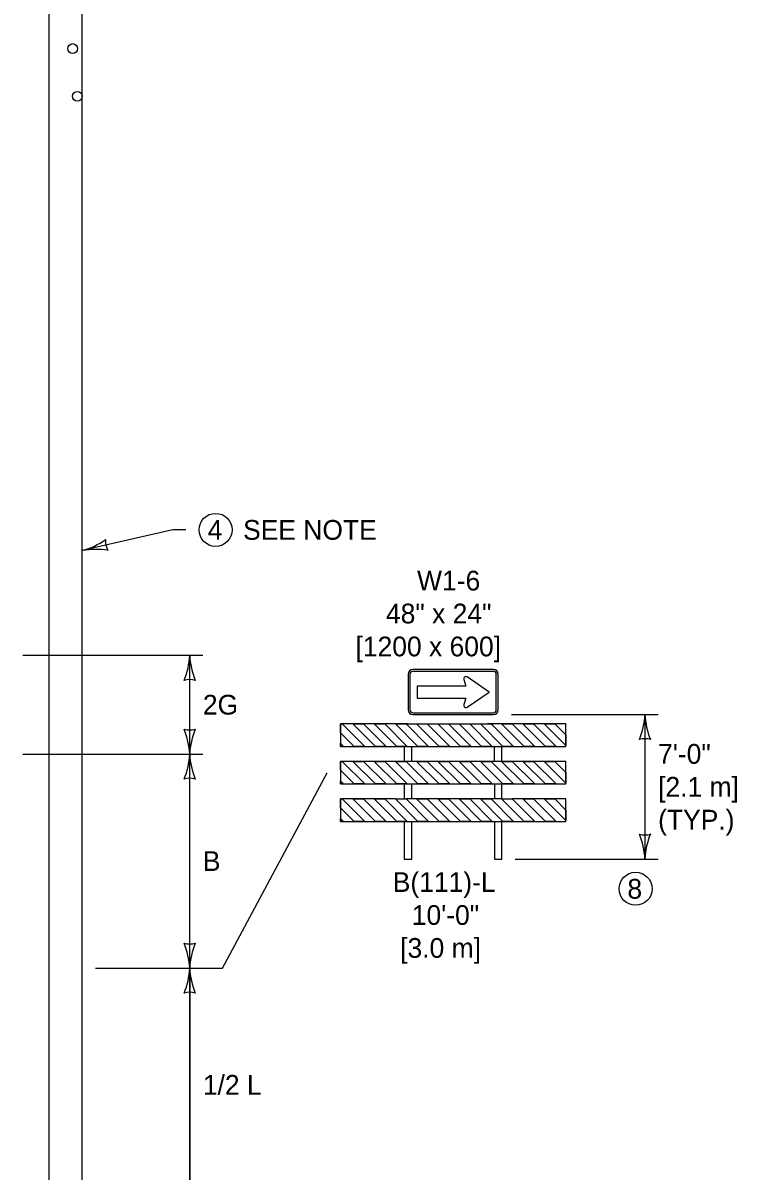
# Model space of a CAD drawing. Extents: x 49991.4 to 50021, y 49987.6 to 50011.4.
# Drawn here: x 50002.932 to 50005.099, y 50003.955 to 50007.442 of the extents above; entities that cross this region are included whole.
import ezdxf

# ---------------------------------------------------------------- set-up
doc = ezdxf.new("R2010")
doc.units = 0
for name, color, linetype in [('Level 1', 7, 'Continuous'), ('Level 2', 7, 'Continuous'), ('Level 3', 7, 'Continuous')]:
    doc.layers.add(name, color=color, linetype=linetype)

msp = doc.modelspace()

# ---------------------------------------------------------------- linework, layer by layer
at = {"layer": 'Level 1'}
for p, q in [((50003.0115, 50000.5714), (50003.0115, 50010.7538)), ((50003.1115, 50000.5714), (50003.1115, 50010.7538)), ((50004.3597, 50005.4783), (50004.1146, 50005.4783)), ((50004.3597, 50005.4726), (50004.1146, 50005.4726)), ((50004.1003, 50005.464), (50004.1003, 50005.3557)), ((50004.106, 50005.464), (50004.106, 50005.3557)), ((50004.2696, 50005.4477), (50004.276, 50005.4281)), ((50004.3466, 50005.4099), (50004.2801, 50005.4556)), ((50004.3682, 50005.3557), (50004.3682, 50005.464)), ((50004.3739, 50005.3557), (50004.3739, 50005.464)), ((50004.2658, 50005.4281), (50004.1276, 50005.4281)), ((50004.1276, 50005.4281), (50004.1276, 50005.3916)), ((50004.276, 50005.4281), (50004.2658, 50005.4281)), ((50004.2801, 50005.3642), (50004.3466, 50005.4099)), ((50004.1276, 50005.3916), (50004.276, 50005.3916)), ((50004.276, 50005.3916), (50004.2696, 50005.372)), ((50004.1146, 50005.3472), (50004.3597, 50005.3472)), ((50004.1146, 50005.3415), (50004.3597, 50005.3415)), ((50003.9691, 50005.2446), (50003.9007, 50005.313)), ((50003.9007, 50005.313), (50003.9691, 50005.2446)), ((50004.0014, 50005.2446), (50003.933, 50005.313)), ((50004.0014, 50005.2446), (50003.933, 50005.313)), ((50004.0336, 50005.2446), (50003.9652, 50005.313)), ((50003.9652, 50005.313), (50004.0336, 50005.2446)), ((50004.0658, 50005.2446), (50003.9975, 50005.313)), ((50004.0658, 50005.2446), (50003.9975, 50005.313)), ((50004.0981, 50005.2446), (50004.0297, 50005.313)), ((50004.0297, 50005.313), (50004.0981, 50005.2446)), ((50004.1304, 50005.2446), (50004.062, 50005.313)), ((50004.1626, 50005.2446), (50004.0942, 50005.313)), ((50004.0942, 50005.313), (50004.1341, 50005.313)), ((50004.1146, 50005.313), (50004.3597, 50005.313)), ((50004.1948, 50005.2446), (50004.1264, 50005.313)), ((50004.227, 50005.2446), (50004.1586, 50005.313)), ((50004.2592, 50005.2446), (50004.1908, 50005.313)), ((50004.2914, 50005.2446), (50004.223, 50005.313)), ((50004.3236, 50005.2446), (50004.2552, 50005.313)), ((50004.3558, 50005.2446), (50004.2874, 50005.313)), ((50004.3882, 50005.2446), (50004.3198, 50005.313)), ((50004.3739, 50005.313), (50004.3426, 50005.313)), ((50004.4205, 50005.2446), (50004.3521, 50005.313)), ((50004.4527, 50005.2446), (50004.3843, 50005.313)), ((50004.4527, 50005.2446), (50004.3843, 50005.313)), ((50004.4849, 50005.2446), (50004.4165, 50005.313)), ((50004.4165, 50005.313), (50004.4849, 50005.2446)), ((50004.5172, 50005.2446), (50004.4488, 50005.313)), ((50004.5172, 50005.2446), (50004.4488, 50005.313)), ((50004.5494, 50005.2446), (50004.481, 50005.313)), ((50004.481, 50005.313), (50004.5494, 50005.2446)), ((50004.5791, 50005.2472), (50004.5133, 50005.313)), ((50004.5791, 50005.2472), (50004.5133, 50005.313)), ((50004.5791, 50005.2794), (50004.5455, 50005.313)), ((50004.5455, 50005.313), (50004.5791, 50005.2794)), ((50003.9369, 50005.2446), (50003.8951, 50005.2864)), ((50003.9369, 50005.2446), (50003.8951, 50005.2864)), ((50003.9047, 50005.2446), (50003.8951, 50005.2541)), ((50003.8951, 50005.2541), (50003.9047, 50005.2446)), ((50004.1117, 50005.199), (50004.1117, 50005.2446)), ((50004.3625, 50005.199), (50004.3625, 50005.2446)), ((50003.9691, 50005.1307), (50003.9007, 50005.199)), ((50003.9007, 50005.199), (50003.9691, 50005.1307)), ((50004.0014, 50005.1307), (50003.933, 50005.199)), ((50004.0014, 50005.1307), (50003.933, 50005.199)), ((50004.0336, 50005.1307), (50003.9652, 50005.199)), ((50003.9652, 50005.199), (50004.0336, 50005.1307)), ((50004.0658, 50005.1307), (50003.9975, 50005.199)), ((50004.0658, 50005.1307), (50003.9975, 50005.199)), ((50004.0981, 50005.1307), (50004.0297, 50005.199)), ((50004.0297, 50005.199), (50004.0981, 50005.1307)), ((50004.1003, 50005.1607), (50004.062, 50005.199)), ((50004.1003, 50005.1929), (50004.0942, 50005.199)), ((50004.1626, 50005.1307), (50004.1003, 50005.1929)), ((50004.1948, 50005.1307), (50004.1264, 50005.199)), ((50004.227, 50005.1307), (50004.1586, 50005.199)), ((50004.2593, 50005.1307), (50004.1909, 50005.199)), ((50004.2915, 50005.1307), (50004.2232, 50005.199)), ((50004.3237, 50005.1307), (50004.2554, 50005.199)), ((50004.356, 50005.1307), (50004.2876, 50005.199)), ((50004.3882, 50005.1307), (50004.3198, 50005.199)), ((50004.4205, 50005.1307), (50004.3521, 50005.199)), ((50004.4527, 50005.1307), (50004.3843, 50005.199)), ((50004.4527, 50005.1307), (50004.3843, 50005.199)), ((50004.4849, 50005.1307), (50004.4165, 50005.199)), ((50004.4165, 50005.199), (50004.4849, 50005.1307)), ((50004.5172, 50005.1307), (50004.4488, 50005.199)), ((50004.5172, 50005.1307), (50004.4488, 50005.199)), ((50004.5494, 50005.1307), (50004.481, 50005.199)), ((50004.481, 50005.199), (50004.5494, 50005.1307)), ((50004.5791, 50005.1332), (50004.5133, 50005.199)), ((50004.5791, 50005.1332), (50004.5133, 50005.199)), ((50004.5791, 50005.1654), (50004.5455, 50005.199)), ((50004.5455, 50005.199), (50004.5791, 50005.1654)), ((50003.9369, 50005.1307), (50003.8951, 50005.1724)), ((50003.9369, 50005.1307), (50003.8951, 50005.1724)), ((50004.1304, 50005.1307), (50004.1003, 50005.1607)), ((50003.9047, 50005.1307), (50003.8951, 50005.1402)), ((50003.8951, 50005.1402), (50003.9047, 50005.1307)), ((50003.9691, 50005.0167), (50003.9007, 50005.0851)), ((50003.9007, 50005.0851), (50003.9691, 50005.0167)), ((50004.0014, 50005.0167), (50003.933, 50005.0851)), ((50004.0014, 50005.0167), (50003.933, 50005.0851)), ((50004.0336, 50005.0167), (50003.9652, 50005.0851)), ((50003.9652, 50005.0851), (50004.0336, 50005.0167)), ((50004.0658, 50005.0167), (50003.9975, 50005.0851)), ((50004.0658, 50005.0167), (50003.9975, 50005.0851)), ((50004.0981, 50005.0167), (50004.0297, 50005.0851)), ((50004.0297, 50005.0851), (50004.0981, 50005.0167)), ((50004.1304, 50005.0167), (50004.062, 50005.0851)), ((50004.1304, 50005.0167), (50004.062, 50005.0851)), ((50004.1626, 50005.0167), (50004.0942, 50005.0851)), ((50004.0942, 50005.0851), (50004.1626, 50005.0167)), ((50004.1948, 50005.0167), (50004.1264, 50005.0851)), ((50004.1948, 50005.0167), (50004.1264, 50005.0851)), ((50004.227, 50005.0167), (50004.1586, 50005.0851)), ((50004.1586, 50005.0851), (50004.227, 50005.0167)), ((50004.2593, 50005.0167), (50004.1909, 50005.0851)), ((50004.2593, 50005.0167), (50004.1909, 50005.0851)), ((50004.2915, 50005.0167), (50004.2232, 50005.0851)), ((50004.2232, 50005.0851), (50004.2915, 50005.0167)), ((50004.3237, 50005.0167), (50004.2554, 50005.0851)), ((50004.3237, 50005.0167), (50004.2554, 50005.0851)), ((50004.356, 50005.0167), (50004.2876, 50005.0851)), ((50004.2876, 50005.0851), (50004.356, 50005.0167)), ((50004.3882, 50005.0167), (50004.3198, 50005.0851)), ((50004.3882, 50005.0167), (50004.3198, 50005.0851)), ((50004.4205, 50005.0167), (50004.3521, 50005.0851)), ((50004.3521, 50005.0851), (50004.4205, 50005.0167)), ((50004.4527, 50005.0167), (50004.3843, 50005.0851)), ((50004.4527, 50005.0167), (50004.3843, 50005.0851)), ((50004.4849, 50005.0167), (50004.4165, 50005.0851)), ((50004.4165, 50005.0851), (50004.4849, 50005.0167)), ((50004.5172, 50005.0167), (50004.4488, 50005.0851)), ((50004.5172, 50005.0167), (50004.4488, 50005.0851)), ((50004.5494, 50005.0167), (50004.481, 50005.0851)), ((50004.481, 50005.0851), (50004.5494, 50005.0167)), ((50004.5791, 50005.0192), (50004.5133, 50005.0851)), ((50004.5791, 50005.0192), (50004.5133, 50005.0851)), ((50004.5791, 50005.0515), (50004.5455, 50005.0851)), ((50004.5455, 50005.0851), (50004.5791, 50005.0515)), ((50003.9369, 50005.0167), (50003.8951, 50005.0584)), ((50003.9369, 50005.0167), (50003.8951, 50005.0584)), ((50003.9047, 50005.0167), (50003.8951, 50005.0262)), ((50003.8951, 50005.0262), (50003.9047, 50005.0167)), ((50003.4375, 50004.5714), (50003.4375, 50003.8622))]:
    msp.add_line(p, q, dxfattribs=at)
for points in [[(50004.1003, 50005.313), (50003.8951, 50005.313), (50003.8951, 50005.2446), (50004.1003, 50005.2446)], [(50003.8951, 50005.2864), (50003.8951, 50005.313), (50003.9007, 50005.313)], [(50003.933, 50005.313), (50003.9652, 50005.313)], [(50003.9975, 50005.313), (50004.0297, 50005.313)], [(50004.1626, 50005.2446), (50004.1304, 50005.2446), (50004.062, 50005.313), (50004.0942, 50005.313), (50004.1626, 50005.2446)], [(50004.1003, 50005.2446), (50004.5791, 50005.2446), (50004.5791, 50005.313), (50004.3739, 50005.313)], [(50004.1264, 50005.313), (50004.1341, 50005.313), (50004.1586, 50005.313), (50004.227, 50005.2446), (50004.1948, 50005.2446), (50004.1264, 50005.313)], [(50004.1908, 50005.313), (50004.223, 50005.313), (50004.2914, 50005.2446), (50004.2592, 50005.2446), (50004.1908, 50005.313)], [(50004.2552, 50005.313), (50004.2874, 50005.313), (50004.3558, 50005.2446), (50004.3236, 50005.2446), (50004.2552, 50005.313)], [(50004.3198, 50005.313), (50004.3426, 50005.313), (50004.3521, 50005.313), (50004.4205, 50005.2446), (50004.3882, 50005.2446), (50004.3198, 50005.313)], [(50004.3843, 50005.313), (50004.4165, 50005.313)], [(50004.4488, 50005.313), (50004.481, 50005.313)], [(50004.5133, 50005.313), (50004.5455, 50005.313)], [(50004.5791, 50005.2794), (50004.5791, 50005.2472)], [(50003.9047, 50005.2446), (50003.8951, 50005.2446), (50003.8951, 50005.2541)], [(50003.9691, 50005.2446), (50003.9369, 50005.2446)], [(50004.0336, 50005.2446), (50004.0014, 50005.2446)], [(50004.0981, 50005.2446), (50004.0658, 50005.2446)], [(50004.0889, 50005.2446), (50004.0889, 50005.199)], [(50004.3853, 50005.199), (50004.3853, 50005.2446)], [(50004.4849, 50005.2446), (50004.4527, 50005.2446)], [(50004.5494, 50005.2446), (50004.5172, 50005.2446)], [(50004.1003, 50005.199), (50003.8951, 50005.199), (50003.8951, 50005.1307), (50004.5791, 50005.1307), (50004.5791, 50005.199), (50004.1003, 50005.199)], [(50003.8951, 50005.1724), (50003.8951, 50005.199), (50003.9007, 50005.199)], [(50003.933, 50005.199), (50003.9652, 50005.199)], [(50003.9975, 50005.199), (50004.0297, 50005.199)], [(50004.1626, 50005.1307), (50004.1304, 50005.1307), (50004.1003, 50005.1607), (50004.062, 50005.199), (50004.0889, 50005.199), (50004.0942, 50005.199), (50004.1003, 50005.1929), (50004.1626, 50005.1307)], [(50004.1264, 50005.199), (50004.1586, 50005.199), (50004.227, 50005.1307), (50004.1948, 50005.1307), (50004.1264, 50005.199)], [(50004.1909, 50005.199), (50004.2232, 50005.199), (50004.2915, 50005.1307), (50004.2593, 50005.1307), (50004.1909, 50005.199)], [(50004.2554, 50005.199), (50004.2876, 50005.199), (50004.356, 50005.1307), (50004.3237, 50005.1307), (50004.2554, 50005.199)], [(50004.3198, 50005.199), (50004.3521, 50005.199), (50004.4205, 50005.1307), (50004.3882, 50005.1307), (50004.3198, 50005.199)], [(50004.3843, 50005.199), (50004.4165, 50005.199)], [(50004.4488, 50005.199), (50004.481, 50005.199)], [(50004.5133, 50005.199), (50004.5455, 50005.199)], [(50004.5791, 50005.1654), (50004.5791, 50005.1332)], [(50003.9047, 50005.1307), (50003.8951, 50005.1307), (50003.8951, 50005.1402)], [(50003.9691, 50005.1307), (50003.9369, 50005.1307)], [(50004.0336, 50005.1307), (50004.0014, 50005.1307)], [(50004.0981, 50005.1307), (50004.0658, 50005.1307)], [(50004.0889, 50005.1307), (50004.0889, 50005.0851)], [(50004.1117, 50005.0851), (50004.1117, 50005.1307)], [(50004.3625, 50005.1307), (50004.3625, 50005.0851)], [(50004.3853, 50005.0851), (50004.3853, 50005.1307)], [(50004.4849, 50005.1307), (50004.4527, 50005.1307)], [(50004.5494, 50005.1307), (50004.5172, 50005.1307)], [(50003.8951, 50005.0584), (50003.8951, 50005.0851), (50003.9007, 50005.0851)], [(50004.062, 50005.0851), (50003.8951, 50005.0851), (50003.8951, 50005.0167), (50004.5791, 50005.0167), (50004.5791, 50005.0851), (50004.4165, 50005.0851)], [(50003.933, 50005.0851), (50003.9652, 50005.0851)], [(50003.9975, 50005.0851), (50004.0297, 50005.0851)], [(50004.062, 50005.0851), (50004.0942, 50005.0851)], [(50004.3843, 50005.0851), (50004.0942, 50005.0851)], [(50004.1264, 50005.0851), (50004.1586, 50005.0851)], [(50004.1909, 50005.0851), (50004.2232, 50005.0851)], [(50004.2554, 50005.0851), (50004.2876, 50005.0851)], [(50004.3198, 50005.0851), (50004.3521, 50005.0851)], [(50004.3843, 50005.0851), (50004.4165, 50005.0851)], [(50004.4488, 50005.0851), (50004.481, 50005.0851)], [(50004.5133, 50005.0851), (50004.5455, 50005.0851)], [(50004.5791, 50005.0515), (50004.5791, 50005.0192)], [(50003.9047, 50005.0167), (50003.8951, 50005.0167), (50003.8951, 50005.0262)], [(50003.9691, 50005.0167), (50003.9369, 50005.0167)], [(50004.0336, 50005.0167), (50004.0014, 50005.0167)], [(50004.0981, 50005.0167), (50004.0658, 50005.0167)], [(50004.0889, 50005.0166), (50004.0889, 50004.9026), (50004.1117, 50004.9026), (50004.1117, 50005.0166)], [(50004.1626, 50005.0167), (50004.1304, 50005.0167)], [(50004.227, 50005.0167), (50004.1948, 50005.0167)], [(50004.2915, 50005.0167), (50004.2593, 50005.0167)], [(50004.356, 50005.0167), (50004.3237, 50005.0167)], [(50004.3625, 50005.0166), (50004.3625, 50004.9026), (50004.3853, 50004.9026), (50004.3853, 50005.0166)], [(50004.4205, 50005.0167), (50004.3882, 50005.0167)], [(50004.4849, 50005.0167), (50004.4527, 50005.0167)], [(50004.5494, 50005.0167), (50004.5172, 50005.0167)]]:
    msp.add_lwpolyline(points, dxfattribs=at)
for centre in [(50003.0824, 50007.3643), (50003.0964, 50007.2194)]:
    msp.add_circle(centre, 0.015, dxfattribs=at)
for centre, radius, start, end in [((50004.1146, 50005.464), 0.0142, 90, 180), ((50004.1146, 50005.464), 0.00855, 90, 180), ((50004.3597, 50005.464), 0.0142, 0, 90), ((50004.3597, 50005.464), 0.00855, 0, 90), ((50004.2762, 50005.4498), 0.00695, 55.4806, 197.9582), ((50004.2762, 50005.3699), 0.00695, 162.0418, 304.5194), ((50004.1146, 50005.3557), 0.0142, 180, 270), ((50004.1146, 50005.3557), 0.00855, 180, 270), ((50004.3597, 50005.3557), 0.0142, 270, 360), ((50004.3597, 50005.3557), 0.00855, 270, 360)]:
    msp.add_arc(centre, radius, start, end, dxfattribs=at)
at = {"layer": 'Level 2'}
for centre in [(50003.5162, 50005.9025), (50004.7911, 50004.8123)]:
    msp.add_circle(centre, 0.0501, dxfattribs=at)
at = {"layer": 'Level 3'}
for p, q in [((50003.3861, 50005.9025), (50003.1115, 50005.8397)), ((50003.4261, 50005.9025), (50003.3861, 50005.9025)), ((50002.9315, 50005.5214), (50003.4775, 50005.5214)), ((50003.4375, 50005.2214), (50003.4375, 50005.5214)), ((50004.4139, 50005.3415), (50004.8593, 50005.3415)), ((50004.8193, 50005.3415), (50004.8193, 50004.9026)), ((50002.9315, 50005.2214), (50003.4775, 50005.2214)), ((50003.4375, 50004.5714), (50003.4375, 50005.2214)), ((50003.5375, 50004.5714), (50003.8551, 50005.1649)), ((50004.4253, 50004.9026), (50004.8593, 50004.9026)), ((50003.1515, 50004.5714), (50003.5375, 50004.5714)), ((50003.222, 50004.5714), (50003.5375, 50004.5714)), ((50003.4375, 50003.8622), (50003.4375, 50004.5714))]:
    msp.add_line(p, q, dxfattribs=at)
for centre, radius, start, end in [((50003.053, 50006.0542), 0.2223, 285.2569, 305.4404), ((50003.2365, 50005.8683), 0.0548, 175.0353, 210.7576), ((50003.1523, 50005.6103), 0.233, 80.8193, 100.0691), ((50003.2154, 50005.5305), 0.2223, 337.456, 357.6395), ((50003.6702, 50005.5329), 0.233, 182.8273, 202.0772), ((50003.4375, 50005.3932), 0.0548, 72.1388, 107.8612), ((50004.5971, 50005.3506), 0.2223, 337.456, 357.6395), ((50005.052, 50005.353), 0.233, 182.8273, 202.0772), ((50003.4375, 50005.3496), 0.0548, 252.1388, 287.8612), ((50003.2048, 50005.2099), 0.233, 2.8273, 22.0772), ((50003.6596, 50005.2122), 0.2223, 157.456, 177.6395), ((50004.8193, 50005.2133), 0.0548, 72.1388, 107.8612), ((50003.2154, 50005.2305), 0.2223, 337.456, 357.6395), ((50003.6702, 50005.2329), 0.233, 182.8273, 202.0772), ((50003.4375, 50005.0932), 0.0548, 72.1388, 107.8612), ((50004.8193, 50005.0308), 0.0548, 252.1388, 287.8612), ((50004.5865, 50004.8911), 0.233, 2.8273, 22.0772), ((50005.0414, 50004.8935), 0.2223, 157.456, 177.6395), ((50003.4375, 50004.6996), 0.0548, 252.1388, 287.8612), ((50003.2048, 50004.5599), 0.233, 2.8273, 22.0772), ((50003.6596, 50004.5622), 0.2223, 157.456, 177.6395), ((50003.2154, 50004.5805), 0.2223, 337.456, 357.6395), ((50003.6702, 50004.5829), 0.233, 182.8273, 202.0772), ((50003.4375, 50004.4432), 0.0548, 72.1388, 107.8612)]:
    msp.add_arc(centre, radius, start, end, dxfattribs=at)

# ---------------------------------------------------------------- texts
at = {"layer": 'Level 2'}
for s, p in [('4', (50003.4922, 50005.8725)), ('SEE NOTE', (50003.5995, 50005.8724))]:
    msp.add_text(s, height=0.06, rotation=360, dxfattribs=at).set_placement(p)
for s, p in [('W1-6', (50004.1277, 50005.7183)), ('48" x 24"', (50004.0333, 50005.6183)), ('[1200 x 600]', (50003.9408, 50005.5183)), ('2G', (50003.4775, 50005.3414)), ('7\'-0"', (50004.8593, 50005.1921)), ('[2.1 m]', (50004.8593, 50005.0921)), ('(TYP.)', (50004.8593, 50004.9921)), ('B', (50003.4775, 50004.8664)), ('B(111)-L', (50004.0539, 50004.8026)), ('8', (50004.7661, 50004.7823)), ('8', (50004.7661, 50004.7823)), ('10\'-0"', (50004.1117, 50004.7026)), ('[3.0 m]', (50004.0764, 50004.6026)), ('1/2 L', (50003.4775, 50004.1868))]:
    msp.add_text(s, height=0.06, dxfattribs=at).set_placement(p)

doc.saveas('drawing.dxf')
